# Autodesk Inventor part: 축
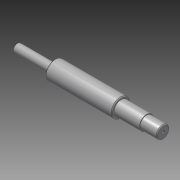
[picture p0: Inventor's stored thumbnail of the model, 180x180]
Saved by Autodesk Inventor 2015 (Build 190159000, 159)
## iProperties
Created: 2016-05
Part Number: 축
Document SubType Name: Modeling
Designer: mduedu
Density: 7.86 g/cm^3
Material: 강철, 연강
Appearance: 강철
Author: mduedu
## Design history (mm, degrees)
sketch "스케치1"
  geometry: L1 (-42, 11)-(-42, 5); L2 (37, 11)-(37, 8.5); L3 (-87, 0)-(87, 0); L4 (-42, 11)-(37, 11); L5 (37, 11)-(37, 8.5); L6 (-42, 11)-(-42, 5); L7 (-42, 5)-(-87, 5); L8 (-87, 5)-(-87, 0); L9 (37, 8.5)-(67, 8.5); L10 (87, 7.5)-(87, 0); L11 (67, 8.5)-(67, 7.5); L12 (67, 7.5)-(87, 7.5); 1 further point
  constraints: 24 end point, 9 perpendicular, 2 midpoint, 1 horizontal
  dimensions: "d0" = 22 diameter of L4 L3; "d1" = 10 diameter of L7 L3; "d2" = 45 distance between parallel lines of L8 L1; "d3" = 50 distance between parallel lines of L10 L2; "d4" = 15 diameter of L12 L3; "d5" = 20 distance between parallel lines of L10 L11; "d29" = 79 distance of L1.start L2.start; "d37" = 17 diameter of L9 L3
revolve "회전1" stored, may be unused: angle "d6" = 90 deg
chamfer "모따기2" distance "d32" = 1; stored, may be unused: second distance "d33" = 2, angle "d34" = 45 deg
node "작업 평면4"
sketch "스케치4"
  geometry: L1 (-5, 2.5)-(5, 2.5); L2 (5, -2.5)-(-5, -2.5); L3 (-10, -6.5)-(-10, 6.5) reference; A1 r 2.5 centre (5, 0) between (5, -2.5) and (5, 2.5); A2 r 2.5 centre (-5, 0) between (-5, 2.5) and (-5, -2.5); 1 further point
  constraints: 4 end point, 4 point on circle, 4 tangent, 2 centre point, 1 horizontal, 1 horizontal alignment, 1 parallel
  dimensions: "d20" = 5 distance between parallel lines of L2 L1; "d21" = 15 dimension on A1 A2; "d35" = 2.5 distance edge to line of A2 L3
extrude "돌출3" cut sketch "스케치4" distance "d23" = 3; taper "d24" = 0 deg
node "작업 평면5"
sketch "스케치5"
  geometry: L1 (22.5, 1.5)-(10, 1.5); L2 (10, -1.5)-(22.5, -1.5); L3 (22.5, 4)-(22.5, -4) reference; A1 r 1.5 centre (10, 0) between (10, 1.5) and (10, -1.5); 3 further points
  constraints: 4 end point, 2 horizontal alignment, 2 point on circle, 2 point on line, 2 tangent, 1 centre point, 1 coincident, 1 horizontal, 1 midpoint
  dimensions: "d25" = 3 distance between parallel lines of L2 L1; "d36" = 14 dimension on A1 L3
extrude "돌출4" cut sketch "스케치5" distance "d27" = 1.8; taper "d28" = 0 deg
hole "구멍1" diameter "d40" = 3.242; stored, may be unused: countersink angle "d44" = 90 deg, drill point angle "d46" = 118 deg; dims "d41" = 10, "d42" = 4, "d43" = 2, "d45" = 12, "d47" = 10, "d48" = 10
node "솔리드1"
